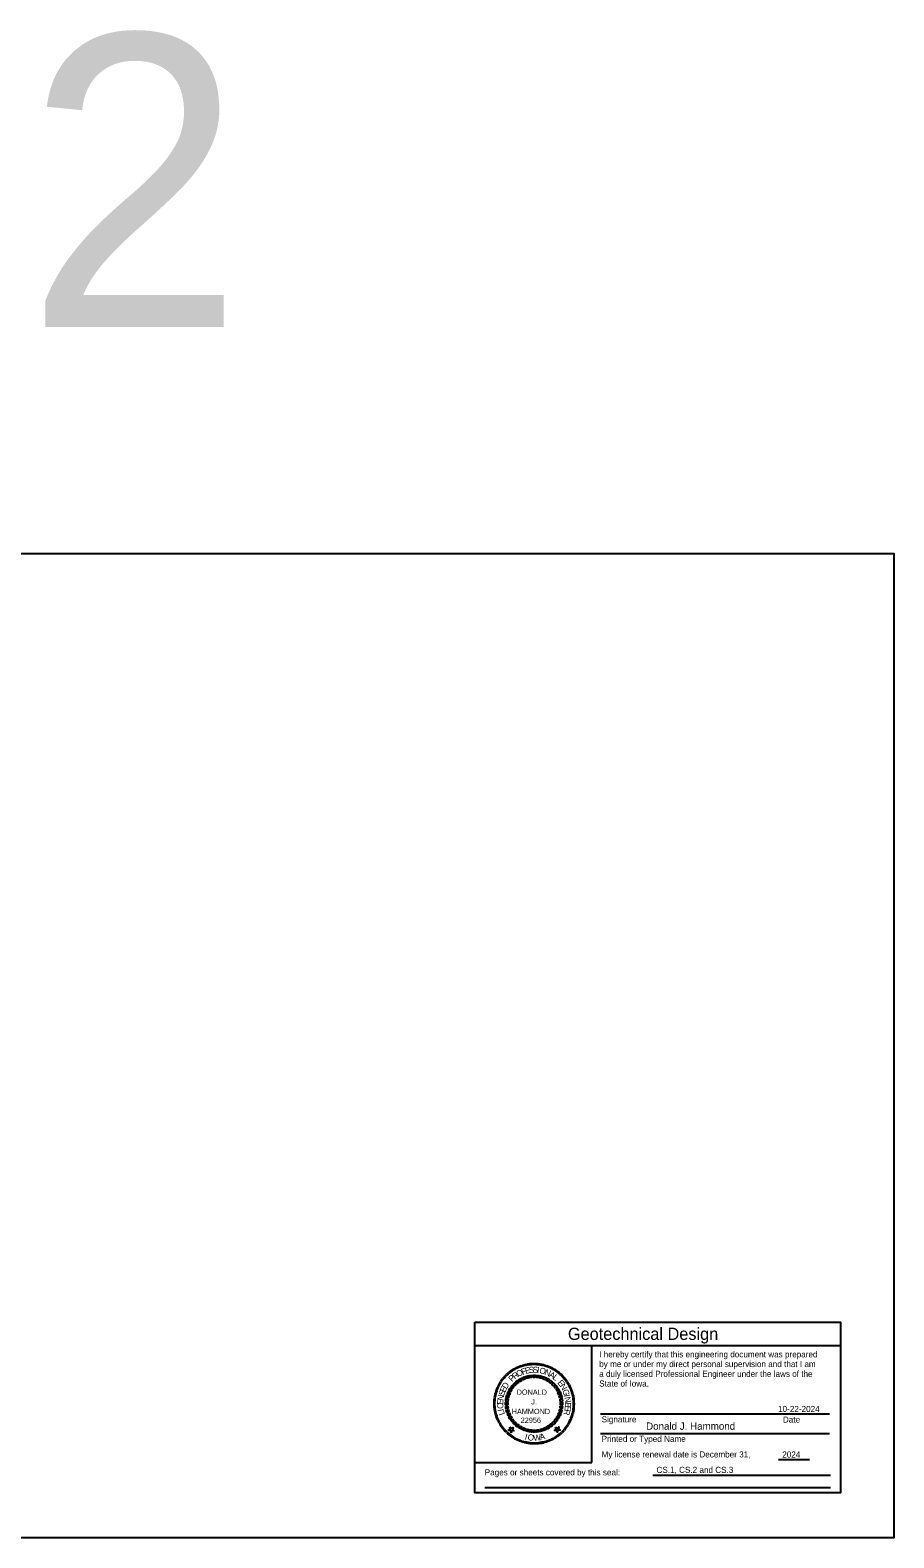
# Model space of a CAD drawing. Extents: x 10040 to 81668, y 7194 to 11018.
# Drawn here: x 15095 to 16868, y 7924 to 11018 of the extents above; entities that cross this region are included whole.
import ezdxf

# ---------------------------------------------------------------- set-up
doc = ezdxf.new("R2010")
doc.units = 0
for name, color, linetype in [('dsnDOTLogo', 7, 'Continuous'), ('DsnShtAttachmentPoints', 7, 'Continuous'), ('dsnShtPlotShapeBatchPrint', 7, 'Continuous'), ('dsnStdBlock', 7, 'Continuous'), ('dsnTextShtTitle', 7, 'Continuous'), ('Level 3', 7, 'Continuous')]:
    doc.layers.add(name, color=color, linetype=linetype)

msp = doc.modelspace()

# ---------------------------------------------------------------- linework, layer by layer
at = {"layer": 'dsnDOTLogo'}
for p, q in [((16007.7, 8318.7), (16757.7, 8318.7)), ((16247.7, 8078.7), (16247.7, 8318.7)), ((16007.7, 8078.7), (16247.7, 8078.7))]:
    msp.add_line(p, q, dxfattribs=at)
msp.add_lwpolyline([(16007.7, 8366.7), (16757.7, 8366.7), (16757.7, 8016.7), (16007.7, 8016.7)], close=True, dxfattribs=at)
at = {"layer": 'dsnShtPlotShapeBatchPrint'}
for p, q in [((16735.4, 8177.5), (16265.4, 8177.5)), ((16735.4, 8137.5), (16265.4, 8137.5)), ((16694.7, 8084), (16630.9, 8084)), ((16372.7, 8052.5), (16737.7, 8052.5)), ((16027.8, 8027.5), (16737.7, 8027.5))]:
    msp.add_line(p, q, dxfattribs=at)
at = {"layer": 'dsnStdBlock'}
for p, q in [((16078.4, 8259.8), (16075.2, 8263.6)), ((16081.1, 8261.9), (16078.1, 8265.9)), ((16083.9, 8264), (16081, 8268.1)), ((16086.8, 8265.9), (16084.1, 8270.1)), ((16089.7, 8267.7), (16087.2, 8272)), ((16092.7, 8269.3), (16090.4, 8273.8)), ((16095.8, 8270.9), (16093.7, 8275.4)), ((16099, 8272.2), (16097.1, 8276.9)), ((16102.2, 8273.5), (16100.5, 8278.2)), ((16105.5, 8274.6), (16103.9, 8279.4)), ((16108.8, 8275.6), (16107.5, 8280.4)), ((16112.1, 8276.4), (16111, 8281.3)), ((16115.5, 8277.1), (16114.6, 8282)), ((16118.9, 8277.6), (16118.2, 8282.5)), ((16122.3, 8278), (16121.9, 8282.9)), ((16125.8, 8278.2), (16125.5, 8283.2)), ((16129.2, 8278.3), (16129.2, 8283.3)), ((16132.7, 8278.2), (16132.9, 8283.2)), ((16136.1, 8278), (16136.5, 8282.9)), ((16139.5, 8277.6), (16140.2, 8282.5)), ((16142.9, 8277.1), (16143.8, 8282)), ((16146.3, 8276.4), (16147.4, 8281.3)), ((16149.7, 8275.6), (16150.9, 8280.4)), ((16153, 8274.6), (16154.5, 8279.4)), ((16156.2, 8273.5), (16157.9, 8278.2)), ((16159.4, 8272.2), (16161.4, 8276.9)), ((16162.6, 8270.9), (16164.7, 8275.4)), ((16165.7, 8269.3), (16168, 8273.8)), ((16168.7, 8267.7), (16171.2, 8272)), ((16171.7, 8265.9), (16174.3, 8270.1)), ((16174.5, 8264), (16177.4, 8268.1)), ((16177.3, 8261.9), (16180.3, 8265.9)), ((16180, 8259.8), (16183.2, 8263.6)), ((16056.2, 8229.5), (16051.6, 8231.4)), ((16057.6, 8232.6), (16053.1, 8234.8)), ((16059.1, 8235.7), (16054.7, 8238)), ((16060.8, 8238.8), (16056.5, 8241.3)), ((16062.6, 8241.7), (16058.4, 8244.4)), ((16064.5, 8244.6), (16060.4, 8247.4)), ((16066.5, 8247.3), (16062.6, 8250.4)), ((16068.7, 8250), (16064.9, 8253.2)), ((16071, 8252.6), (16067.3, 8256)), ((16073.3, 8255.1), (16069.8, 8258.7)), ((16075.8, 8257.5), (16072.5, 8261.2)), ((16182.6, 8257.5), (16186, 8261.2)), ((16185.1, 8255.1), (16188.6, 8258.7)), ((16187.5, 8252.6), (16191.1, 8256)), ((16189.7, 8250), (16193.6, 8253.2)), ((16191.9, 8247.3), (16195.8, 8250.4)), ((16193.9, 8244.6), (16198, 8247.4)), ((16195.8, 8241.7), (16200.1, 8244.4)), ((16197.6, 8238.8), (16202, 8241.3)), ((16199.3, 8235.7), (16203.7, 8238)), ((16200.8, 8232.6), (16205.3, 8234.8)), ((16202.2, 8229.5), (16206.8, 8231.4)), ((16050.3, 8202.7), (16045.3, 8202.9)), ((16050.5, 8206.1), (16045.5, 8206.6)), ((16050.9, 8209.6), (16045.9, 8210.2)), ((16051.4, 8213), (16046.5, 8213.8)), ((16052.1, 8216.4), (16047.2, 8217.4)), ((16052.9, 8219.7), (16048.1, 8221)), ((16053.9, 8223), (16049.1, 8224.5)), ((16055, 8226.3), (16050.3, 8228)), ((16203.4, 8226.3), (16208.1, 8228)), ((16204.6, 8223), (16209.3, 8224.5)), ((16205.5, 8219.7), (16210.3, 8221)), ((16206.3, 8216.4), (16211.2, 8217.4)), ((16207, 8213), (16211.9, 8213.8)), ((16207.5, 8209.6), (16212.5, 8210.2)), ((16207.9, 8206.1), (16212.9, 8206.6)), ((16208.1, 8202.7), (16213.1, 8202.9)), ((16050.2, 8199.3), (16045.2, 8199.3)), ((16050.3, 8195.8), (16045.3, 8195.6)), ((16050.5, 8192.4), (16045.5, 8191.9)), ((16050.9, 8188.9), (16045.9, 8188.3)), ((16051.4, 8185.5), (16046.5, 8184.7)), ((16052.1, 8182.2), (16047.2, 8181.1)), ((16052.9, 8178.8), (16048.1, 8177.5)), ((16053.9, 8175.5), (16049.1, 8174)), ((16055, 8172.2), (16050.3, 8170.5)), ((16056.2, 8169), (16051.6, 8167.1)), ((16202.2, 8169), (16206.8, 8167.1)), ((16203.4, 8172.2), (16208.1, 8170.5)), ((16204.6, 8175.5), (16209.3, 8174)), ((16205.5, 8178.8), (16210.3, 8177.5)), ((16206.3, 8182.2), (16211.2, 8181.1)), ((16207, 8185.5), (16211.9, 8184.7)), ((16207.5, 8188.9), (16212.5, 8188.3)), ((16207.9, 8192.4), (16212.9, 8191.9)), ((16208.1, 8195.8), (16213.1, 8195.6)), ((16208.2, 8199.3), (16213.2, 8199.3)), ((16057.6, 8165.9), (16053.1, 8163.8)), ((16059.1, 8162.8), (16054.7, 8160.5)), ((16060.8, 8159.8), (16056.5, 8157.3)), ((16062.6, 8156.8), (16058.4, 8154.1)), ((16064.5, 8153.9), (16060.4, 8151.1)), ((16066.5, 8151.2), (16062.6, 8148.1)), ((16068.7, 8148.5), (16064.9, 8145.3)), ((16071, 8145.9), (16067.3, 8142.5)), ((16073.3, 8143.4), (16069.8, 8139.9)), ((16075.8, 8141), (16072.5, 8137.3)), ((16078.4, 8138.7), (16075.2, 8134.9)), ((16180, 8138.7), (16183.2, 8134.9)), ((16182.6, 8141), (16186, 8137.3)), ((16185.1, 8143.4), (16188.6, 8139.9)), ((16187.5, 8145.9), (16191.1, 8142.5)), ((16189.7, 8148.5), (16193.6, 8145.3)), ((16191.9, 8151.2), (16195.8, 8148.1)), ((16193.9, 8153.9), (16198, 8151.1)), ((16195.8, 8156.8), (16200.1, 8154.1)), ((16197.6, 8159.8), (16202, 8157.3)), ((16199.3, 8162.8), (16203.7, 8160.5)), ((16200.8, 8165.9), (16205.3, 8163.8)), ((16081.1, 8136.6), (16078.1, 8132.6)), ((16083.9, 8134.5), (16081, 8130.4)), ((16086.8, 8132.6), (16084.1, 8128.4)), ((16089.7, 8130.8), (16087.2, 8126.5)), ((16092.7, 8129.2), (16090.4, 8124.7)), ((16095.8, 8127.7), (16093.7, 8123.1)), ((16099, 8126.3), (16097.1, 8121.7)), ((16102.2, 8125), (16100.5, 8120.3)), ((16105.5, 8123.9), (16103.9, 8119.1)), ((16108.8, 8122.9), (16107.5, 8118.1)), ((16112.1, 8122.1), (16111, 8117.2)), ((16115.5, 8121.5), (16114.6, 8116.5)), ((16118.9, 8120.9), (16118.2, 8116)), ((16122.3, 8120.6), (16121.9, 8115.6)), ((16125.8, 8120.3), (16125.5, 8115.3)), ((16129.2, 8120.3), (16129.2, 8115.3)), ((16132.7, 8120.3), (16132.9, 8115.3)), ((16136.1, 8120.6), (16136.5, 8115.6)), ((16139.5, 8120.9), (16140.2, 8116)), ((16142.9, 8121.5), (16143.8, 8116.5)), ((16146.3, 8122.1), (16147.4, 8117.2)), ((16149.7, 8122.9), (16150.9, 8118.1)), ((16153, 8123.9), (16154.5, 8119.1)), ((16156.2, 8125), (16157.9, 8120.3)), ((16159.4, 8126.3), (16161.4, 8121.6)), ((16162.6, 8127.7), (16164.7, 8123.1)), ((16165.7, 8129.2), (16168, 8124.7)), ((16168.7, 8130.8), (16171.2, 8126.5)), ((16171.7, 8132.6), (16174.3, 8128.4)), ((16174.5, 8134.5), (16177.4, 8130.4)), ((16177.3, 8136.6), (16180.3, 8132.6))]:
    msp.add_line(p, q, dxfattribs=at)
for points in [[(16083.6, 8228.2), (16081.3, 8224.3), (16077.4, 8226.6), (16079.7, 8230.5)], [(16087.7, 8233.9), (16085, 8230.3), (16081.4, 8233.1), (16084.2, 8236.7)], [(16092.6, 8239), (16089.4, 8235.8), (16086.3, 8239), (16089.4, 8242.2)], [(16098.1, 8243.5), (16094.5, 8240.7), (16091.8, 8244.3), (16095.4, 8247)], [(16104.2, 8247.1), (16100.3, 8244.9), (16098, 8248.8), (16101.9, 8251)], [(16110.6, 8250), (16106.5, 8248.3), (16104.7, 8252.4), (16108.9, 8254.2)], [(16117.4, 8252), (16113.1, 8250.8), (16111.9, 8255.2), (16116.2, 8256.3)], [(16124.4, 8253.1), (16119.9, 8252.5), (16119.3, 8257), (16123.8, 8257.5)], [(16131.5, 8253.3), (16127, 8253.3), (16127, 8257.8), (16131.5, 8257.8)], [(16138.5, 8252.5), (16134, 8253.1), (16134.6, 8257.5), (16139.1, 8257)], [(16145.4, 8250.8), (16141, 8252), (16142.2, 8256.3), (16146.5, 8255.2)], [(16152, 8248.3), (16147.8, 8250), (16149.5, 8254.2), (16153.7, 8252.4)], [(16158.2, 8244.9), (16154.3, 8247.1), (16156.5, 8251), (16160.4, 8248.8)], [(16163.9, 8240.7), (16160.3, 8243.5), (16163, 8247), (16166.6, 8244.3)], [(16169, 8235.8), (16165.8, 8239), (16169, 8242.2), (16172.2, 8239)], [(16173.4, 8230.3), (16170.7, 8233.9), (16174.2, 8236.7), (16177, 8233.1)], [(16177.1, 8224.3), (16174.8, 8228.2), (16178.7, 8230.5), (16181, 8226.6)], [(16075.2, 8201.5), (16075.2, 8197), (16070.7, 8197), (16070.7, 8201.5)], [(16076, 8208.5), (16075.4, 8204.1), (16070.9, 8204.7), (16071.5, 8209.1)], [(16077.6, 8215.4), (16076.5, 8211.1), (16072.1, 8212.2), (16073.3, 8216.6)], [(16080.2, 8222), (16078.5, 8217.8), (16074.3, 8219.6), (16076, 8223.7)], [(16180, 8217.8), (16178.2, 8222), (16182.4, 8223.7), (16184.1, 8219.6)], [(16182, 8211.1), (16180.8, 8215.4), (16185.1, 8216.6), (16186.3, 8212.2)], [(16183, 8204.1), (16182.5, 8208.5), (16186.9, 8209.1), (16187.5, 8204.7)], [(16183.2, 8197), (16183.2, 8201.5), (16187.7, 8201.5), (16187.7, 8197)], [(16075.4, 8194.4), (16076, 8190), (16071.5, 8189.4), (16070.9, 8193.9)], [(16076.5, 8187.5), (16077.6, 8183.1), (16073.3, 8181.9), (16072.1, 8186.3)], [(16078.5, 8180.7), (16080.2, 8176.5), (16076, 8174.8), (16074.3, 8178.9)], [(16081.3, 8174.2), (16083.6, 8170.3), (16079.7, 8168.1), (16077.4, 8172)], [(16174.8, 8170.3), (16177.1, 8174.2), (16181, 8172), (16178.7, 8168.1)], [(16178.2, 8176.5), (16180, 8180.7), (16184.1, 8178.9), (16182.4, 8174.8)], [(16180.8, 8183.1), (16181.9, 8187.5), (16186.3, 8186.3), (16185.1, 8181.9)], [(16182.5, 8190), (16183, 8194.4), (16187.5, 8193.9), (16186.9, 8189.4)], [(16079.5, 8151), (16082.6, 8148.1), (16086.3, 8150.3), (16084.6, 8146.4), (16087.8, 8143.5), (16083.5, 8144), (16081.8, 8140.1), (16080.9, 8144.3), (16076.7, 8144.7), (16080.4, 8146.8)], [(16085, 8168.2), (16087.7, 8164.6), (16084.2, 8161.9), (16081.4, 8165.4)], [(16089.4, 8162.7), (16092.6, 8159.5), (16089.4, 8156.3), (16086.3, 8159.5)], [(16094.5, 8157.8), (16098.1, 8155), (16095.4, 8151.5), (16091.8, 8154.2)], [(16100.3, 8153.6), (16104.2, 8151.4), (16101.9, 8147.5), (16098, 8149.7)], [(16106.5, 8150.2), (16110.6, 8148.5), (16108.9, 8144.3), (16104.7, 8146.1)], [(16113.1, 8147.7), (16117.4, 8146.5), (16116.2, 8142.2), (16111.9, 8143.3)], [(16119.9, 8146), (16124.4, 8145.4), (16123.8, 8141), (16119.3, 8141.6)], [(16127, 8145.3), (16131.5, 8145.3), (16131.5, 8140.8), (16127, 8140.8)], [(16134, 8145.4), (16138.5, 8146), (16139.1, 8141.5), (16134.6, 8141)], [(16141, 8146.5), (16145.4, 8147.7), (16146.5, 8143.3), (16142.2, 8142.2)], [(16147.8, 8148.5), (16152, 8150.2), (16153.7, 8146.1), (16149.5, 8144.3)], [(16154.3, 8151.4), (16158.2, 8153.6), (16160.4, 8149.7), (16156.5, 8147.5)], [(16160.3, 8155), (16163.9, 8157.8), (16166.6, 8154.2), (16163, 8151.5)], [(16165.8, 8159.5), (16169, 8162.7), (16172.2, 8159.5), (16169, 8156.3)], [(16170.7, 8164.6), (16173.4, 8168.2), (16177, 8165.4), (16174.2, 8161.9)], [(16172.9, 8151), (16176.5, 8148.7), (16179.8, 8151.5), (16178.7, 8147.4), (16182.4, 8145.1), (16178.1, 8144.8), (16177.1, 8140.7), (16175.5, 8144.6), (16171.2, 8144.3), (16174.5, 8147.1)]]:
    msp.add_lwpolyline(points, close=True, dxfattribs=at)
at = {"layer": 'Level 3'}
msp.add_lwpolyline([(13732.5, 9944), (16867.5, 9944), (16867.5, 7924), (13732.5, 7924)], close=True, dxfattribs=at)

# ---------------------------------------------------------------- texts
at = {"layer": 'DsnShtAttachmentPoints'}
for s, p in [('DONALD', (16093.4, 8217.6)), ('J.', (16123.4, 8197.8)), ('HAMMOND', (16083.3, 8178)), ('22956', (16101.8, 8159.9))]:
    msp.add_text(s, height=10.8, dxfattribs=at).set_placement(p)
at = {"layer": 'dsnStdBlock'}
for s, rotation, p in [('R', 36.1562, (16089.5, 8248.7)), ('O', 28.9649, (16096.7, 8253.7)), ('F', 21.7736, (16105.7, 8258.1)), ('E', 14.5823, (16112.2, 8260.3)), ('S', 7.3911, (16119.1, 8261.9)), ('S', 0.1998, (16126.4, 8262.6)), ('I', 353.0085, (16134.5, 8262.5)), ('O', 345.8172, (16139.1, 8262.1)), ('N', 338.6259, (16149.5, 8259.4)), ('A', 331.4346, (16158.7, 8255.3)), ('E', 64.9213, (16069.6, 8221.5)), ('D', 57.7301, (16072.6, 8228.3)), ('P', 43.3475, (16083.7, 8243.5)), ('L', 324.2434, (16166.1, 8250.8)), ('E', 309.8608, (16176.3, 8241.8)), ('N', 302.6695, (16181.2, 8235.6)), ('E', 86.4952, (16065.6, 8196.9)), ('C', 93.6865, (16066.4, 8189.1)), ('N', 79.3039, (16065.8, 8204.8)), ('S', 72.1126, (16067.5, 8214.4)), ('G', 288.2869, (16186.9, 8226.6)), ('I', 281.0956, (16190.3, 8216.9)), ('N', 281.0956, (16191.2, 8212.2)), ('E', 266.2773, (16192.9, 8202.8)), ('I', 100.8778, (16067.4, 8185)), ('L', 108.069, (16069.5, 8177.9)), ('R', 259.086, (16191.7, 8188.6)), ('E', 266.2773, (16192.5, 8195.6)), ('I', 345.2906, (16109.2, 8126)), ('A', 14.0557, (16142.1, 8124.3)), ('O', 352.4819, (16115.3, 8124.6)), ('W', 6.8645, (16128.3, 8122.7))]:
    msp.add_text(s, height=12.5, rotation=rotation, dxfattribs=at).set_placement(p)
at = {"layer": 'dsnTextShtTitle'}
for s, height, p in [('2', 600, (15085.9, 10409.2)), ('Geotechnical Design', 25, (16198.6, 8330.2)), ('I hereby certify that this engineering document was prepared', 12.48, (16262.8, 8294.4)), ('a duly licensed Professional Engineer under the laws of the', 12.48, (16262.8, 8254.4)), ('by me or under my direct personal supervision and that I am', 12.48, (16262.8, 8274.4)), ('State of Iowa.', 12.48, (16262.8, 8234.5)), ('Signature', 12.5, (16267.7, 8161)), ('10-22-2024', 12.48, (16629.9, 8182.3)), ('Date', 12.5, (16639.8, 8160.5)), ('Donald J. Hammond', 15, (16359, 8145.8)), ('Printed or Typed Name', 12.5, (16267.7, 8121)), ('My license renewal date is December 31,', 12.5, (16267.7, 8089)), ('2024', 12.48, (16638.5, 8088.8)), ('Pages or sheets covered by this seal:', 12.5, (16027.8, 8052.2)), ('CS.1, CS.2 and CS.3', 12.48, (16380.4, 8057.3))]:
    msp.add_text(s, height=height, dxfattribs=at).set_placement(p)

doc.saveas('drawing.dxf')
